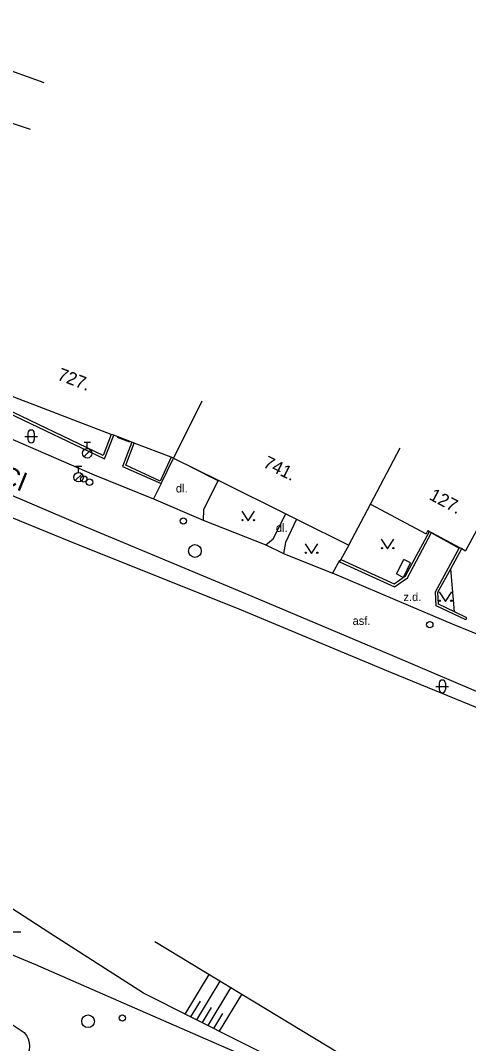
# Model space of a CAD drawing. Extents: x -539244 to -537359, y -1183785 to -1181851.
# Drawn here: x -538489.1 to -538453.9, y -1183313.6 to -1183233.2 of the extents above; entities that cross this region are included whole.
import ezdxf

# ---------------------------------------------------------------- set-up
doc = ezdxf.new("R2010")
doc.units = 0
for name, color, linetype in [('Vrstva 10', 7, 'Continuous'), ('Vrstva 11', 7, 'Continuous'), ('Vrstva 14', 7, 'Continuous'), ('Vrstva 15', 7, 'Continuous'), ('Vrstva 21', 7, 'Continuous'), ('Vrstva 24', 7, 'Continuous'), ('Vrstva 27', 7, 'Continuous'), ('Vrstva 28', 7, 'Continuous'), ('Vrstva 36', 7, 'Continuous'), ('Vrstva 40', 7, 'Continuous'), ('Vrstva 47', 7, 'Continuous'), ('Vrstva 49', 7, 'Continuous'), ('Vrstva 5', 7, 'Continuous'), ('Vrstva 6', 7, 'Continuous'), ('Vrstva 7', 7, 'Continuous'), ('Vrstva 9', 7, 'Continuous')]:
    doc.layers.add(name, color=color, linetype=linetype)

msp = doc.modelspace()

# ---------------------------------------------------------------- linework, layer by layer
at = {"layer": 'Vrstva 10'}
for p, q in [((-538500.98, -1183261.26), (-538483.33, -1183268.9)), ((-538502.63, -1183265.03), (-538484.63, -1183272.71)), ((-538483.33, -1183268.9), (-538478.67, -1183270.79)), ((-538478.67, -1183270.79), (-538474.76, -1183272.45)), ((-538474.76, -1183272.45), (-538469.83, -1183274.4)), ((-538484.63, -1183272.71), (-538471.44, -1183278.21)), ((-538458.44, -1183279.23), (-538464.6, -1183276.63)), ((-538471.44, -1183278.21), (-538459.71, -1183283.18)), ((-538455.18, -1183280.63), (-538458.44, -1183279.23)), ((-538450.44, -1183282.57), (-538455.18, -1183280.63)), ((-538459.71, -1183283.18), (-538446.8, -1183288.66)), ((-538487.91, -1183307.39), (-538499.1, -1183302.78)), ((-538480.14, -1183310.82), (-538487.91, -1183307.39)), ((-538465.12, -1183317.35), (-538480.14, -1183310.82))]:
    msp.add_line(p, q, dxfattribs=at)
msp.add_lwpolyline([(-538469.83, -1183274.4), (-538468.46, -1183275.07), (-538464.6, -1183276.63)], dxfattribs=at)
at = {"layer": 'Vrstva 11'}
for p, q in [((-538488.33, -1183241.75), (-538501.45, -1183237.42)), ((-538478.06, -1183269.57), (-538478.67, -1183270.79)), ((-538464.05, -1183275.62), (-538464.6, -1183276.63)), ((-538455.024, -1183279.654), (-538455.308, -1183276.274)), ((-538489.93, -1183311.98), (-538488.83, -1183312.72))]:
    msp.add_line(p, q, dxfattribs=at)
for points in [[(-538473.594, -1183269.318), (-538474.74, -1183271.65), (-538474.76, -1183272.45)], [(-538469.83, -1183274.4), (-538469.27, -1183273.92), (-538468.27, -1183271.96)], [(-538467.433, -1183272.375), (-538468.31, -1183274.22), (-538468.46, -1183275.07)], [(-538488.83, -1183312.72), (-538488.645, -1183312.953), (-538488.51, -1183313.219), (-538488.43, -1183313.505), (-538488.408, -1183313.802), (-538488.445, -1183314.098), (-538488.54, -1183314.38)]]:
    msp.add_lwpolyline(points, dxfattribs=at)
at = {"layer": 'Vrstva 14'}
for p, q in [((-538486.81, -1183304.91), (-538496.97, -1183298.37)), ((-538479.45, -1183309.62), (-538486.81, -1183304.91)), ((-538463.17, -1183314.92), (-538478.56, -1183305.59)), ((-538464.97, -1183316.91), (-538479.45, -1183309.62))]:
    msp.add_line(p, q, dxfattribs=at)
at = {"layer": 'Vrstva 15'}
for p, q in [((-538476.172, -1183311.27), (-538474.296, -1183308.175)), ((-538475.277, -1183311.721), (-538473.441, -1183308.693)), ((-538474.381, -1183312.172), (-538472.586, -1183309.212)), ((-538473.485, -1183312.623), (-538471.731, -1183309.73)), ((-538475.725, -1183311.496), (-538474.982, -1183310.271)), ((-538474.829, -1183311.947), (-538474.102, -1183310.749)), ((-538473.933, -1183312.398), (-538473.223, -1183311.227))]:
    msp.add_line(p, q, dxfattribs=at)
at = {"layer": 'Vrstva 21'}
msp.add_line((-538506.06, -1183231.39), (-538487.28, -1183238.06), dxfattribs=at)
at = {"layer": 'Vrstva 24'}
for p, q in [((-538459.568, -1183276.685), (-538459.008, -1183275.545)), ((-538458.47, -1183275.81), (-538459.008, -1183275.545)), ((-538459.03, -1183276.95), (-538458.47, -1183275.81)), ((-538459.568, -1183276.685), (-538459.03, -1183276.95))]:
    msp.add_line(p, q, dxfattribs=at)
at = {"layer": 'Vrstva 27'}
for centre in [(-538475.42, -1183274.88), (-538483.81, -1183311.84)]:
    msp.add_circle(centre, 0.5, dxfattribs=at)
at = {"layer": 'Vrstva 28'}
for p, q in [((-538484.13, -1183266.325), (-538483.63, -1183266.325)), ((-538483.88, -1183266.825), (-538483.88, -1183266.325)), ((-538484.138, -1183267.472), (-538483.608, -1183266.942)), ((-538484.81, -1183268.204), (-538484.31, -1183268.204)), ((-538484.56, -1183268.704), (-538484.56, -1183268.204)), ((-538484.819, -1183269.351), (-538484.289, -1183268.821))]:
    msp.add_line(p, q, dxfattribs=at)
for centre, radius in [((-538483.88, -1183267.2), 0.375), ((-538484.56, -1183269.08), 0.375), ((-538484.15, -1183269.22), 0.25), ((-538483.7, -1183269.47), 0.25), ((-538476.33, -1183272.52), 0.25), ((-538456.96, -1183280.67), 0.25), ((-538481.12, -1183311.58), 0.25)]:
    msp.add_circle(centre, radius, dxfattribs=at)
at = {"layer": 'Vrstva 36'}
for p, q in [((-538488.79, -1183265.873), (-538487.79, -1183265.873)), ((-538488.541, -1183265.622), (-538488.541, -1183266.123)), ((-538488.04, -1183265.622), (-538488.04, -1183266.123)), ((-538456.226, -1183285.267), (-538456.226, -1183285.768)), ((-538455.725, -1183285.267), (-538455.725, -1183285.768)), ((-538456.475, -1183285.518), (-538455.475, -1183285.518)), ((-538490.089, -1183304.818), (-538489.089, -1183304.818))]:
    msp.add_line(p, q, dxfattribs=at)
for points in [[(-538471.726, -1183271.753), (-538471.226, -1183272.503), (-538470.726, -1183271.753)], [(-538460.771, -1183273.96), (-538460.271, -1183274.71), (-538459.771, -1183273.96)], [(-538466.746, -1183274.315), (-538466.246, -1183275.065), (-538465.746, -1183274.315)], [(-538456.218, -1183278.088), (-538455.718, -1183278.838), (-538455.218, -1183278.088)]]:
    msp.add_lwpolyline(points, dxfattribs=at)
for centre in [(-538471.676, -1183272.453), (-538470.777, -1183272.453), (-538460.721, -1183274.66), (-538459.822, -1183274.66), (-538466.696, -1183275.015), (-538465.797, -1183275.015), (-538456.168, -1183278.788), (-538455.269, -1183278.788)]:
    msp.add_circle(centre, 0.05, dxfattribs=at)
for centre, start, end in [((-538488.29, -1183265.623), 0, 180), ((-538488.29, -1183266.123), 180, 0), ((-538455.975, -1183285.268), 0, 180), ((-538455.975, -1183285.768), 180, 0)]:
    msp.add_arc(centre, 0.25, start, end, dxfattribs=at)
at = {"layer": 'Vrstva 5'}
for p, q in [((-538481.988, -1183265.713), (-538491.797, -1183261.964)), ((-538474.878, -1183263.101), (-538477.1, -1183267.58)), ((-538481.801, -1183265.784), (-538481.988, -1183265.713)), ((-538480.379, -1183266.327), (-538481.801, -1183265.784)), ((-538480.192, -1183266.398), (-538480.379, -1183266.327)), ((-538477.287, -1183267.509), (-538480.192, -1183266.398)), ((-538461.62, -1183271.19), (-538459.274, -1183266.774)), ((-538477.1, -1183267.58), (-538477.287, -1183267.509)), ((-538473.061, -1183269.583), (-538468.484, -1183271.854)), ((-538451.781, -1183270.452), (-538454.14, -1183274.86)), ((-538463.33, -1183274.41), (-538461.62, -1183271.19)), ((-538461.62, -1183271.19), (-538457.25, -1183273.53)), ((-538467.32, -1183272.431), (-538463.33, -1183274.41)), ((-538457.111, -1183273.27), (-538457.25, -1183273.53)), ((-538457.111, -1183273.27), (-538456.987, -1183273.337)), ((-538456.987, -1183273.337), (-538456.811, -1183273.431)), ((-538456.811, -1183273.431), (-538454.625, -1183274.601)), ((-538454.625, -1183274.601), (-538454.448, -1183274.695)), ((-538454.448, -1183274.695), (-538454.14, -1183274.86))]:
    msp.add_line(p, q, dxfattribs=at)
for points in [[(-538477.1, -1183267.58), (-538473.594, -1183269.318), (-538473.061, -1183269.583)], [(-538468.484, -1183271.854), (-538468.27, -1183271.96), (-538467.433, -1183272.375), (-538467.32, -1183272.431)]]:
    msp.add_lwpolyline(points, dxfattribs=at)
at = {"layer": 'Vrstva 6'}
for p, q in [((-538481.52, -1183265.93), (-538480.56, -1183266.29)), ((-538468.27, -1183271.96), (-538467.33, -1183272.44)), ((-538456.82, -1183273.46), (-538454.64, -1183274.65))]:
    msp.add_line(p, q, dxfattribs=at)
msp.add_lwpolyline([(-538475.79, -1183268.25), (-538473.604, -1183269.338), (-538473.56, -1183269.36)], dxfattribs=at)
at = {"layer": 'Vrstva 7'}
for p, q in [((-538482.619, -1183267.366), (-538492.127, -1183262.829)), ((-538490.09, -1183264.023), (-538482.51, -1183267.64)), ((-538481.988, -1183265.713), (-538482.619, -1183267.366)), ((-538482.51, -1183267.64), (-538481.801, -1183265.784)), ((-538458.71, -1183276.98), (-538456.811, -1183273.431)), ((-538463.33, -1183274.41), (-538463.953, -1183275.544)), ((-538463.953, -1183275.544), (-538464.05, -1183275.72)), ((-538454.12, -1183280.3), (-538454.035, -1183280.119))]:
    msp.add_line(p, q, dxfattribs=at)
for points in [[(-538480.379, -1183266.327), (-538481.11, -1183268.24), (-538478.06, -1183269.57), (-538477.1, -1183267.58)], [(-538477.287, -1183267.509), (-538478.139, -1183269.394), (-538480.856, -1183268.137), (-538480.192, -1183266.398)], [(-538463.953, -1183275.544), (-538459.751, -1183277.47), (-538458.864, -1183276.844), (-538456.987, -1183273.337)], [(-538454.12, -1183280.3), (-538456.46, -1183279.2), (-538456.52, -1183278.08), (-538454.625, -1183274.601)], [(-538454.035, -1183280.119), (-538455.024, -1183279.654), (-538456.267, -1183279.07), (-538456.317, -1183278.126), (-538455.308, -1183276.274), (-538454.448, -1183274.695)], [(-538464.05, -1183275.72), (-538459.73, -1183277.7), (-538458.71, -1183276.98)]]:
    msp.add_lwpolyline(points, dxfattribs=at)
at = {"layer": 'Vrstva 9'}
for p, q in [((-538485.3, -1183274.12), (-538503.5, -1183266.64)), ((-538471.75, -1183279.53), (-538485.3, -1183274.12)), ((-538460.01, -1183284.44), (-538471.75, -1183279.53)), ((-538447.19, -1183289.7), (-538460.01, -1183284.44))]:
    msp.add_line(p, q, dxfattribs=at)

# ---------------------------------------------------------------- texts
at = {"layer": 'Vrstva 40'}
for s, p in [('dl.', (-538476.91, -1183270.28)), ('dl.', (-538469.05, -1183273.376)), ('z.d.', (-538459.025, -1183278.815)), ('asf.', (-538463.024, -1183280.685))]:
    msp.add_text(s, height=0.65, dxfattribs=at).set_placement(p)
at = {"layer": 'Vrstva 47'}
for s, rotation, p in [('727.', 339.08977, (-538486.293, -1183261.391)), ('741.', 333.61832, (-538470.127, -1183268.248)), ('127.', 331.83233, (-538457.077, -1183270.787))]:
    msp.add_text(s, height=1, rotation=rotation, dxfattribs=at).set_placement(p)
at = {"layer": 'Vrstva 49'}
msp.add_text('ul. VE STRHANCI', height=1.5, rotation=337.92395, dxfattribs=at).set_placement((-538503.969, -1183264.159))

doc.saveas('drawing.dxf')
